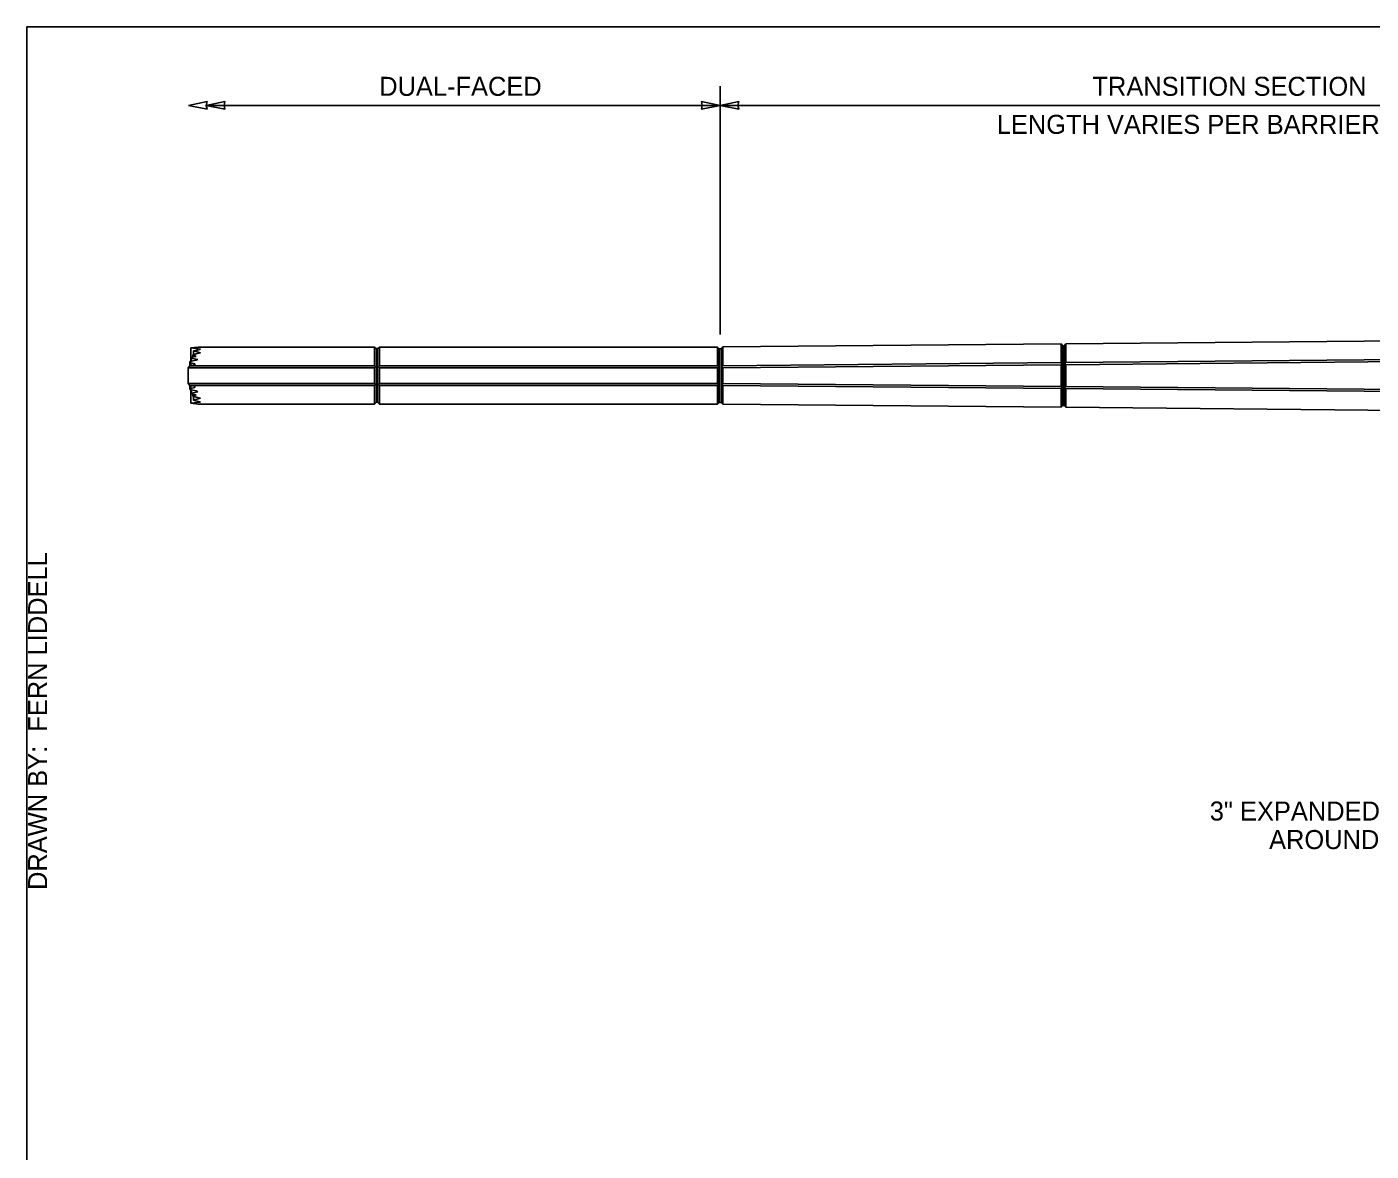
# Model space of a CAD drawing. Extents: x 99862 to 103151, y 100000 to 102076.
# Drawn here: x 99862 to 100993, y 101130 to 102076 of the extents above; entities that cross this region are included whole.
import ezdxf

# ---------------------------------------------------------------- set-up
doc = ezdxf.new("R2010")
doc.units = 0
for name, color, linetype in [('Level 1', 7, 'Continuous'), ('Level 15', 7, 'Continuous'), ('Level 2', 7, 'Continuous'), ('Level 20', 7, 'Continuous'), ('Level 3', 7, 'Continuous'), ('Level 62', 7, 'Continuous')]:
    doc.layers.add(name, color=color, linetype=linetype)

msp = doc.modelspace()

# ---------------------------------------------------------------- linework, layer by layer
at = {"layer": 'Level 1'}
msp.add_lwpolyline([(99862, 99999.5), (103151, 99999.5), (103151, 102075.5), (99862, 102075.5)], close=True, dxfattribs=at)
at = {"layer": 'Level 15'}
for p, q in [((100445.2, 101816.6), (100445.2, 102025.5)), ((100013.3, 102009.5), (100445.2, 102009.5)), ((100445.2, 102009.5), (101310.7, 102009.5))]:
    msp.add_line(p, q, dxfattribs=at)
for points in [[(99997.9, 102009.5), (100013.6, 102006.4), (100012.9, 102009.5), (100013.6, 102012.6)], [(100012.9, 102009.5), (100028.6, 102006.4), (100027.9, 102009.5), (100028.6, 102012.6)], [(100445.2, 102009.5), (100429.5, 102012.6), (100430.2, 102009.5), (100429.5, 102006.4)], [(100445.2, 102009.5), (100461, 102006.4), (100460.2, 102009.5), (100461, 102012.6)]]:
    msp.add_lwpolyline(points, close=True, dxfattribs=at)
at = {"layer": 'Level 2'}
for p, q in [((100736, 101808.8), (101020, 101811.5)), ((100000, 101805.4), (100006, 101806.1)), ((100008, 101804.4), (100000, 101805.4)), ((100000, 101797.6), (100000, 101805.4)), ((100000, 101797.6), (100004.3, 101798.3)), ((100001.6, 101799.6), (100004.3, 101800.4)), ((100004.3, 101798.3), (100001.6, 101799.6)), ((100001.6, 101797.8), (100001.6, 101799.6)), ((100002.1, 101802.9), (100005.3, 101803.6)), ((100002.1, 101799.8), (100002.1, 101802.9)), ((100008, 101801.2), (100002.1, 101802.9)), ((100004.3, 101800.4), (100008, 101801.2)), ((100005.3, 101803.6), (100008, 101804.4)), ((100154.5, 101806.1), (100006, 101806.1)), ((100154.5, 101806.1), (100156, 101804.6)), ((100154.5, 101790.4), (100154.5, 101806.1)), ((100157, 101804.6), (100156, 101804.6)), ((100156, 101804.6), (100156, 101788.9)), ((100158.5, 101806.1), (100157, 101804.6)), ((100157, 101804.6), (100157, 101788.9)), ((100158.5, 101806.1), (100204.5, 101806.1)), ((100158.5, 101790.4), (100158.5, 101806.1)), ((100443, 101806.1), (100204.5, 101806.1)), ((100444.5, 101804.6), (100443, 101806.1)), ((100443, 101806.1), (100443, 101790.4)), ((100444.5, 101788.9), (100444.5, 101804.6)), ((100446, 101804.6), (100447.5, 101806.2)), ((100447.5, 101806.2), (100732, 101808.8)), ((100733.5, 101807.3), (100732, 101808.8)), ((100733.5, 101807.3), (100734.5, 101807.3)), ((100736, 101808.8), (100734.5, 101807.3)), ((99997.8, 101788.6), (99999.2, 101790.4)), ((100154.5, 101788.6), (99997.8, 101788.6)), ((99997.8, 101775.6), (99997.8, 101788.6)), ((99999, 101794), (100004.3, 101795.1)), ((99999, 101790.1), (99999, 101794)), ((100000, 101792.9), (99999, 101794)), ((99999.2, 101790.4), (100003.2, 101791.2)), ((100154.5, 101790.4), (99999.2, 101790.4)), ((100000.5, 101796.9), (100000, 101797.6)), ((100000, 101794.2), (100000, 101797.6)), ((100000, 101790.6), (100000, 101792.9)), ((100003.2, 101792.1), (100000, 101792.9)), ((100005.9, 101795.8), (100000.5, 101796.9)), ((100000.5, 101794.4), (100000.5, 101796.9)), ((100003.2, 101791.2), (100003.2, 101792.1)), ((100004.3, 101795.1), (100005.9, 101795.8)), ((100155.2, 101789.5), (100154.5, 101790.4)), ((100154.5, 101788.6), (100155.2, 101789.5)), ((100154.5, 101775.6), (100154.5, 101788.6)), ((100155.2, 101789.5), (100156, 101788.9)), ((100157, 101788.9), (100156, 101788.9)), ((100156, 101788.9), (100156, 101775.4)), ((100157.7, 101789.5), (100157, 101788.9)), ((100157, 101788.9), (100157, 101775.4)), ((100157.7, 101789.5), (100158.5, 101790.4)), ((100158.5, 101788.6), (100157.7, 101789.5)), ((100158.5, 101790.4), (100443, 101790.4)), ((100158.5, 101788.6), (100443, 101788.6)), ((100158.5, 101775.6), (100158.5, 101788.6)), ((100443.7, 101789.5), (100443, 101790.4)), ((100443, 101788.6), (100443.7, 101789.5)), ((100443, 101788.6), (100443, 101775.6)), ((100444.5, 101788.9), (100443.7, 101789.5)), ((100444.5, 101775.4), (100444.5, 101788.9)), ((99999.2, 101773.9), (99997.8, 101775.6)), ((100154.5, 101775.6), (99997.9, 101775.6)), ((100155.2, 101774.8), (100154.5, 101775.6)), ((100155.2, 101774.8), (100156, 101775.4)), ((100156, 101775.4), (100156, 101759.7)), ((100157, 101775.4), (100156, 101775.4)), ((100157, 101775.4), (100157, 101759.7)), ((100157.7, 101774.8), (100157, 101775.4)), ((100157.7, 101774.8), (100158.5, 101775.6)), ((100158.5, 101775.6), (100443, 101775.6)), ((100443.7, 101774.8), (100443, 101775.6)), ((100443.7, 101774.8), (100444.5, 101775.4)), ((100444.5, 101759.6), (100444.5, 101775.4)), ((99999, 101770.3), (99999, 101774.2)), ((99999, 101770.3), (100000, 101771.4)), ((100004.3, 101769.2), (99999, 101770.3)), ((100003.2, 101773.1), (99999.2, 101773.9)), ((100154.5, 101773.9), (99999.2, 101773.9)), ((100000, 101771.4), (100000, 101773.7)), ((100000, 101771.4), (100003.2, 101772.2)), ((100000, 101766.7), (100000, 101770)), ((100000, 101766.7), (100000.5, 101767.4)), ((100000, 101758.9), (100000, 101766.7)), ((100004.3, 101766), (100000, 101766.7)), ((100000.5, 101767.4), (100000.5, 101769.9)), ((100000.5, 101767.4), (100005.9, 101768.5)), ((100001.6, 101764.7), (100001.6, 101766.5)), ((100001.6, 101764.7), (100004.3, 101766)), ((100004.3, 101763.9), (100001.6, 101764.7)), ((100002.1, 101761.4), (100002.1, 101764.5)), ((100003.2, 101772.2), (100003.2, 101773.1)), ((100005.9, 101768.5), (100004.3, 101769.2)), ((100008, 101763.1), (100004.3, 101763.9)), ((100154.5, 101773.9), (100155.2, 101774.8)), ((100154.5, 101758.1), (100154.5, 101773.9)), ((100158.5, 101773.9), (100157.7, 101774.8)), ((100158.5, 101773.9), (100443, 101773.9)), ((100158.5, 101758.1), (100158.5, 101773.9)), ((100443, 101773.9), (100443.7, 101774.8)), ((100443, 101773.9), (100443, 101758.1)), ((100000, 101758.9), (100008, 101759.9)), ((100006, 101758.1), (100000, 101758.9)), ((100002.1, 101761.4), (100008, 101763.1)), ((100005.3, 101760.7), (100002.1, 101761.4)), ((100008, 101759.9), (100005.3, 101760.7)), ((100154.5, 101758.1), (100006, 101758.1)), ((100156, 101759.7), (100154.5, 101758.1)), ((100157, 101759.7), (100156, 101759.7)), ((100157, 101759.7), (100158.5, 101758.1)), ((100158.5, 101758.1), (100204.5, 101758.1)), ((100204.5, 101758.1), (100443, 101758.1)), ((100443, 101758.1), (100444.5, 101759.6)), ((100447.5, 101758.1), (100446, 101759.6)), ((100447.5, 101758.1), (100732, 101755.5)), ((100732, 101755.5), (100733.5, 101757)), ((100733.5, 101757), (100734.5, 101757)), ((100734.5, 101757), (100736, 101755.5)), ((100736, 101755.5), (101020, 101752.8))]:
    msp.add_line(p, q, dxfattribs=at)
at = {"layer": 'Level 3'}
for p, q in [((100446, 101804.6), (100444.5, 101804.6)), ((100444.5, 101804.6), (100444.5, 101788.9)), ((100444.5, 101804.6), (100446, 101804.6)), ((100446, 101788.9), (100446, 101804.6)), ((100446, 101788.9), (100446, 101804.6)), ((100447.5, 101806.2), (100447.5, 101790.4)), ((100732, 101793.1), (100732, 101808.8)), ((100733.5, 101807.3), (100733.5, 101791.6)), ((100734.5, 101791.6), (100734.5, 101807.3)), ((100736, 101808.8), (100736, 101793.1)), ((100444.5, 101788.9), (100444.5, 101775.4)), ((100446.7, 101789.5), (100446, 101788.9)), ((100446, 101775.4), (100446, 101788.9)), ((100446, 101775.4), (100446, 101788.9)), ((100447.5, 101790.4), (100446.7, 101789.5)), ((100446.7, 101789.5), (100447.5, 101788.7)), ((100447.5, 101790.4), (100732, 101793.1)), ((100732, 101791.3), (100447.5, 101788.7)), ((100447.5, 101788.7), (100447.5, 101775.6)), ((100732, 101793.1), (100732.7, 101792.2)), ((100732.7, 101792.2), (100732, 101791.3)), ((100732, 101773), (100732, 101791.3)), ((100733.5, 101791.6), (100732.7, 101792.2)), ((100733.5, 101791.6), (100733.5, 101772.7)), ((100734.5, 101791.6), (100733.5, 101791.6)), ((100735.2, 101792.2), (100734.5, 101791.6)), ((100734.5, 101772.7), (100734.5, 101791.6)), ((100736, 101793.1), (100735.2, 101792.2)), ((100735.2, 101792.2), (100736, 101791.3)), ((100736, 101793.1), (101020, 101795.7)), ((101020, 101794), (100736, 101791.3)), ((100736, 101791.3), (100736, 101773)), ((100444.5, 101775.4), (100444.5, 101759.6)), ((100446, 101759.6), (100446, 101775.4)), ((100446, 101759.6), (100446, 101775.4)), ((100446, 101775.4), (100446.7, 101774.8)), ((100447.5, 101775.6), (100446.7, 101774.8)), ((100447.5, 101775.6), (100732, 101773)), ((100446.7, 101774.8), (100447.5, 101773.9)), ((100447.5, 101773.9), (100447.5, 101758.1)), ((100732, 101771.2), (100447.5, 101773.9)), ((100732, 101773), (100732.7, 101772.1)), ((100732.7, 101772.1), (100732, 101771.2)), ((100732, 101755.5), (100732, 101771.2)), ((100732.7, 101772.1), (100733.5, 101772.7)), ((100733.5, 101772.7), (100733.5, 101757)), ((100734.5, 101772.7), (100733.5, 101772.7)), ((100734.5, 101757), (100734.5, 101772.7)), ((100734.5, 101772.7), (100735.2, 101772.1)), ((100736, 101773), (100735.2, 101772.1)), ((100735.2, 101772.1), (100736, 101771.2)), ((100736, 101773), (101020, 101770.3)), ((100736, 101771.2), (100736, 101755.5)), ((101020, 101768.6), (100736, 101771.2)), ((100444.5, 101759.6), (100446, 101759.6)), ((100444.5, 101759.6), (100446, 101759.6))]:
    msp.add_line(p, q, dxfattribs=at)

# ---------------------------------------------------------------- texts
at = {"layer": 'Level 20'}
for s, p in [('DUAL-FACED', (100158.4, 102017.5)), ('TRANSITION SECTION', (100758.4, 102017.5)), ('LENGTH VARIES PER BARRIER TYPE', (100677.9, 101985.5)), ('3" EXPANDED POLYSTYRENE ', (100857.1, 101407.8)), ('AROUND COLUMN (TYP.)', (100907, 101383.8))]:
    msp.add_text(s, height=16, dxfattribs=at).set_placement(p)
at = {"layer": 'Level 62'}
msp.add_text('DRAWN BY:  FERN LIDDELL', height=16, rotation=90, dxfattribs=at).set_placement((99879, 101349.4))

doc.saveas('drawing.dxf')
